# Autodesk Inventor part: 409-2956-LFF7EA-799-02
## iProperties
Created: 2010-11
Part Number: 409-2956-LFF7EA-799-02
Material: 3/4" OD TUBE - SS
Document SubType Name: Modeling
Designer: S. Boerckel
Engineer: Steve Boerckel
Mass: 309.983 g
Surface Area: 466.545 cm^2
Volume: 38.3643 cm^3
Density: 8.08 g/cm^3
Description: DRAIN TUBING
User Status: CUT/TUBE BEND
Length: 22.316 in
Author: S. Boerckel
Revision Number: 0
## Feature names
1. Sweep1
